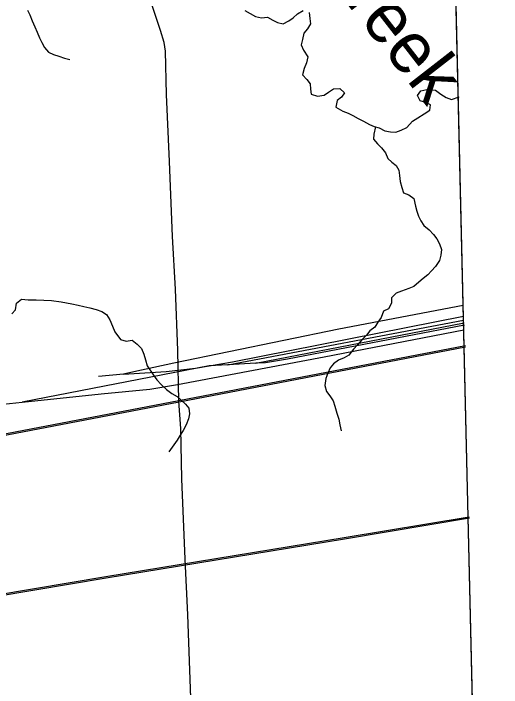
# Model space of a CAD drawing. Extents: x -5.4 to 71.3, y -12 to 22.
# Drawn here: x 6.076 to 6.976, y 16.448 to 17.692 of the extents above; entities that cross this region are included whole.
import ezdxf

# ---------------------------------------------------------------- set-up
doc = ezdxf.new("R2010")
doc.units = 0
for name, color, linetype in [('GM_X_City_Street', 7, 'Continuous'), ('GM_X_Minor_River', 7, 'Continuous'), ('GM_X_Minor_River_Text', 7, 'Continuous'), ('GM_X_Rail_Line', 7, 'Continuous'), ('PM_X_Surveyed_Line', 7, 'Continuous'), ('SH_Cut_Line', 7, 'Continuous')]:
    doc.layers.add(name, color=color, linetype=linetype)

msp = doc.modelspace()

# ---------------------------------------------------------------- linework, layer by layer
at = {"layer": 'GM_X_City_Street'}
msp.add_lwpolyline([(6.407, 16.3093), (6.397, 16.5818), (6.3923, 16.6844), (6.3863, 16.833), (6.3845, 16.926), (6.3806, 16.9764), (6.3788, 17.0696), (6.3745, 17.1827), (6.3691, 17.2804), (6.3634, 17.4185), (6.3581, 17.5422), (6.3558, 17.6221), (6.3538, 17.6381), (6.3466, 17.6604), (6.3163, 17.7524), (6.2919, 17.8272), (6.2367, 18.0086), (6.229, 18.0496), (6.227, 18.0742), (6.2167, 18.1032), (6.1889, 18.1893), (6.1537, 18.2812)], dxfattribs=at)
at = {"layer": 'GM_X_Minor_River'}
for points in [[(6.1018, 17.6978), (6.1058, 17.6891), (6.1101, 17.6782), (6.1153, 17.6673), (6.1196, 17.6575), (6.124, 17.6469), (6.1283, 17.6383), (6.1331, 17.6292), (6.1401, 17.6202), (6.1493, 17.6162), (6.1596, 17.613), (6.1695, 17.6094), (6.1798, 17.6069)], [(6.5025, 17.6974), (6.5121, 17.6915), (6.5221, 17.6863), (6.5332, 17.6839), (6.5442, 17.6848), (6.5538, 17.6797), (6.5626, 17.6749), (6.5733, 17.6729), (6.5838, 17.678), (6.5913, 17.6838), (6.5996, 17.6912), (6.6101, 17.6971)], [(6.6208, 17.6935), (6.6222, 17.6822), (6.6235, 17.6727), (6.6179, 17.6631), (6.6112, 17.6553), (6.6084, 17.6439), (6.6063, 17.634), (6.6107, 17.6238), (6.6185, 17.6118)], [(6.6185, 17.6118), (6.616, 17.6007), (6.6116, 17.59), (6.6088, 17.5785), (6.6166, 17.57), (6.6228, 17.5621), (6.6233, 17.5522), (6.6246, 17.5428), (6.6361, 17.5392), (6.6486, 17.5409), (6.6569, 17.5468), (6.6659, 17.5527), (6.6777, 17.5533), (6.6862, 17.5451), (6.6806, 17.537), (6.6724, 17.5311), (6.6703, 17.5189), (6.683, 17.5116), (6.6929, 17.5076), (6.7017, 17.5036), (6.7114, 17.4981), (6.7209, 17.4929), (6.7321, 17.4871), (6.7409, 17.4834), (6.7501, 17.4806), (6.7608, 17.4754), (6.7707, 17.4734), (6.781, 17.4728), (6.7904, 17.4764), (6.8014, 17.4815), (6.8118, 17.4928), (6.8216, 17.4994), (6.8332, 17.5065), (6.8434, 17.5131), (6.8447, 17.523), (6.8363, 17.5274), (6.8256, 17.5306), (6.8208, 17.5404), (6.8272, 17.5489), (6.8381, 17.5514), (6.8438, 17.5507)], [(6.8438, 17.5507), (6.8541, 17.5502), (6.8638, 17.5431), (6.8734, 17.5369), (6.8833, 17.5329), (6.8974, 17.5377), (6.8974, 17.5377)], [(6.7436, 17.4826), (6.74, 17.4693), (6.7398, 17.4595), (6.7468, 17.4509), (6.7545, 17.4438), (6.7619, 17.4344), (6.7663, 17.4243), (6.7732, 17.4172), (6.7817, 17.4113), (6.7864, 17.4026), (6.7877, 17.3928), (6.7891, 17.3814), (6.7919, 17.3704), (6.7951, 17.3606), (6.8051, 17.357), (6.8139, 17.3503), (6.8172, 17.3363), (6.8193, 17.3269), (6.8225, 17.3178), (6.8272, 17.3088), (6.8327, 17.3002), (6.842, 17.2923), (6.8501, 17.2838), (6.8567, 17.2759), (6.8614, 17.2665), (6.865, 17.2563), (6.8641, 17.246), (6.8612, 17.2357), (6.8542, 17.225), (6.8467, 17.2165), (6.8396, 17.2095), (6.831, 17.2029), (6.8231, 17.1959), (6.8138, 17.1877), (6.8047, 17.1845), (6.7915, 17.1793), (6.7813, 17.1757), (6.7731, 17.1668), (6.7729, 17.1569), (6.767, 17.1469), (6.7583, 17.1422), (6.7536, 17.1307), (6.7476, 17.1223), (6.7421, 17.1127), (6.7331, 17.106), (6.7268, 17.0983), (6.7182, 17.0894), (6.71, 17.0801), (6.7029, 17.072), (6.6943, 17.0612), (6.6857, 17.0561), (6.6751, 17.0521), (6.6661, 17.0451), (6.6598, 17.0378), (6.6554, 17.0278), (6.6517, 17.0183), (6.6501, 17.0049), (6.6529, 16.9944), (6.6591, 16.9861), (6.665, 16.9767), (6.6682, 16.9669), (6.6719, 16.9541), (6.6755, 16.9431), (6.6776, 16.9325), (6.68, 16.9216)], [(6.0725, 17.1377), (6.0792, 17.1447), (6.0813, 17.1569), (6.0907, 17.1647), (6.1029, 17.163), (6.1177, 17.1633), (6.1314, 17.1628), (6.1459, 17.1619), (6.1638, 17.1596), (6.1737, 17.1575), (6.1836, 17.1557), (6.1947, 17.1533), (6.2057, 17.1512), (6.2168, 17.1488), (6.2283, 17.1456), (6.2386, 17.1419), (6.2474, 17.1364), (6.2537, 17.1263), (6.2585, 17.1146), (6.2628, 17.104), (6.273, 17.0898), (6.2833, 17.0869), (6.2943, 17.0891), (6.3039, 17.0813), (6.3116, 17.0734), (6.316, 17.0629), (6.3192, 17.0523), (6.3221, 17.0417), (6.3342, 17.0241), (6.34, 17.0158), (6.3482, 17.0069), (6.3582, 16.9979), (6.3678, 16.9905), (6.3778, 16.9846), (6.3852, 16.9783), (6.3929, 16.9709), (6.3991, 16.9634), (6.4004, 16.9532), (6.3987, 16.9436), (6.3939, 16.9325), (6.3884, 16.9222), (6.3832, 16.9137), (6.3777, 16.9045), (6.3714, 16.8957), (6.3625, 16.883)]]:
    msp.add_lwpolyline(points, dxfattribs=at)
at = {"layer": 'GM_X_Minor_River_Text'}
msp.add_lwpolyline([(2.1, 14.1), (6.9755, 14.1), (6.9588, 14.9805), (6.9517, 15.3029), (6.9368, 15.8488), (6.9366, 15.8554), (6.9363, 15.8669), (6.9247, 16.3154), (6.8724, 18.5494)], dxfattribs=at)
at = {"layer": 'GM_X_Rail_Line'}
for p, q in [((6.4708, 17.0433), (6.9056, 17.126)), ((6.5229, 17.0463), (6.9071, 17.1208)), ((6.4708, 17.0433), (6.4367, 17.0414)), ((6.5229, 17.0463), (6.4708, 17.0433)), ((6.4367, 17.0414), (6.0917, 16.9745)), ((6.2784, 17.0262), (6.2323, 17.0216))]:
    msp.add_line(p, q, dxfattribs=at)
for points in [[(6.905, 17.1529), (6.6759, 17.1091), (6.3714, 17.0463), (6.2978, 17.0302), (6.2784, 17.0262)], [(6.4367, 17.0414), (6.4796, 17.0486), (6.9054, 17.1334)], [(6.9077, 17.1163), (6.5809, 17.0539), (6.5404, 17.0473), (6.5229, 17.0463)], [(6.0917, 16.9745), (6.2377, 16.9897), (6.327, 16.9984), (6.3783, 17.007), (6.6486, 17.0581), (6.9062, 17.108)], [(2.1, 15.8148), (2.2084, 15.85), (2.7845, 16.0381), (3.5525, 16.2895), (3.9999, 16.4363), (4.2764, 16.5289), (4.4956, 16.5982), (4.5851, 16.6274), (4.6324, 16.6405), (4.714, 16.6576), (4.912, 16.6969), (5.1624, 16.7441), (5.4756, 16.8049), (5.8762, 16.8809), (6.3808, 16.9775), (6.9091, 17.0789)], [(2.1, 15.8124), (2.2091, 15.8478), (2.7852, 16.0359), (3.5533, 16.2873), (4.0006, 16.4341), (4.2771, 16.5267), (4.4963, 16.5961), (4.5857, 16.6252), (4.633, 16.6383), (4.7144, 16.6554), (4.9125, 16.6946), (5.1628, 16.7419), (5.476, 16.8027), (5.8766, 16.8787), (6.3813, 16.9752), (6.9095, 17.0766)], [(6.2784, 17.0262), (6.3573, 17.0312), (6.4112, 17.0371), (6.4367, 17.0414)], [(5.4639, 16.8668), (5.4642, 16.865), (5.467, 16.8471), (5.4704, 16.8323), (5.4754, 16.8061), (5.4764, 16.8499), (5.4836, 16.8783), (5.4971, 16.9), (5.5151, 16.9187), (5.5371, 16.9323), (5.558, 16.9389), (5.5802, 16.9421), (5.7428, 16.9493), (5.7657, 16.949), (5.8047, 16.9498), (5.8481, 16.9505), (5.9331, 16.9577), (6.0328, 16.9683), (6.0917, 16.9745)], [(3.3871, 16.0994), (3.4501, 16.1267), (3.5086, 16.1514), (3.5658, 16.1721), (3.6599, 16.2046), (3.7755, 16.2341), (3.8457, 16.2501), (3.9075, 16.2615), (3.9736, 16.2726), (4.1646, 16.304), (4.529, 16.3625), (4.5998, 16.3768), (4.6369, 16.3827), (5.1487, 16.4632), (5.2955, 16.4899), (5.3539, 16.4998), (5.6216, 16.5451), (5.8366, 16.5815), (6.2464, 16.6504), (6.6862, 16.7225), (6.9167, 16.7608)], [(5.6296, 16.5465), (5.6573, 16.5535), (5.8362, 16.5838), (6.2461, 16.6527), (6.6858, 16.7248), (6.9163, 16.7631)]]:
    msp.add_lwpolyline(points, dxfattribs=at)
at = {"layer": 'PM_X_Surveyed_Line'}
msp.add_lwpolyline([(2.1, 14.1), (6.9757, 14.1), (6.955, 15.1854), (6.9275, 16.1897), (6.8702, 18.6385)], dxfattribs=at)
at = {"layer": 'SH_Cut_Line'}
msp.add_lwpolyline([(2.1, 14.1), (6.9755, 14.1), (6.9588, 14.9805), (6.9517, 15.3029), (6.9368, 15.8488), (6.9366, 15.8554), (6.9363, 15.8669), (6.9247, 16.3154), (6.8724, 18.5494)], dxfattribs=at)

# ---------------------------------------------------------------- texts
at = {"layer": 'GM_X_Minor_River_Text'}
msp.add_text('Creek', height=0.09475, rotation=307.85, dxfattribs=at).set_placement((6.6312, 17.7858))

doc.saveas('drawing.dxf')
